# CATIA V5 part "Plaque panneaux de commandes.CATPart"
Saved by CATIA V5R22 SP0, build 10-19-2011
Part number: Plaque panneaux de commandes
Bounding box of the stored display mesh (mm): x 0 to 10, y -428 to 428, z -100 to 100
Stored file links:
  D:\PER\CAO_PER_MODIF_2025\CAO_PER_pick&place_2024P\Cadre\Plaque panneaux de commandes.CATPart
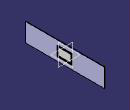
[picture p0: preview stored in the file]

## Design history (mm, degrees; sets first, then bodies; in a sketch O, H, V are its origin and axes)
Body1 (main body)
  Sketch1 on yz-plane, origin (0, 0, 0), H (0, 1, 0), V (0, 0, 1)
    line L1 (428, 100) -> (428, -100)
    line L2 (428, -100) -> (-428, -100)
    line L3 (-428, -100) -> (-428, 100)
    line L4 (-428, 100) -> (428, 100)
    distance L4 L2 = 200
    distance L1 L3 = 856
    vertical: L1 V, L3 V
    horizontal: L2 H, L4 H
    equidistance: L1 L3 O, L2 L4 O
  Pad1: profile Sketch1, direction (1, 0, 0), length 5
  Sketch2 on end face of Pad1, origin (5, 0, 0), H (0, 1, 0), V (0, 0, 1)
    line L1 (80, 52.5) -> (80, -52.5)
    line L2 (80, -52.5) -> (-80, -52.5)
    line L3 (-80, -52.5) -> (-80, 52.5)
    line L4 (-80, 52.5) -> (80, 52.5)
    length L4 = 160
    length L1 = 105
    vertical: L1 V, L3 V
    horizontal: L2 H, L4 H
    equidistance: L1 L3 O, L2 L4 O
  Pad2: profile Sketch2, direction (1, 0, 0), length 5
  Sketch3 on end face of Pad1, origin (5, 0, 0), H (0, 1, 0), V (0, 0, 1)
    line L1 (70, 42.5) -> (70, -42.5)
    line L2 (70, -42.5) -> (-70, -42.5)
    line L3 (-70, -42.5) -> (-70, 42.5)
    line L4 (-70, 42.5) -> (70, 42.5)
    reference projected line E1 (80, 52.5) -> (-80, 52.5) from edge [face of Pad2 from Sketch2.L4 | end face of Pad2]
    reference projected line E2 (80, -52.5) -> (80, 52.5) from edge [face of Pad2 from Sketch2.L1 | end face of Pad2]
    distance L4 E1 = 10
    distance E2 L1 = 10
    vertical: L1 V, L3 V
    horizontal: L2 H, L4 H
    equidistance: L1 L3 O, L2 L4 O
  Pocket1: profile Sketch3, direction (1, 0, 0), length 5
